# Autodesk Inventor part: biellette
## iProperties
Shininess: 20.0
Angle Display Precision: 2
Document Length Units: 11269
Document Angle Units: 11279
Document Time Units: 11290
Document Mass Units: 11283
Document Length Units Precision: 3
Document Angle Units Precision: 2
Compacted: True
Created: 2002-04
Part Number: biellette
Material: Par défaut
Document SubType Name: Modélisation
Designer: thchene
Density: 0.0
Volumn: 0.0
Area: 0.0
PropertySet Name: Model Information
Control State: 0
Master: False
Checked Out: False
Author: thchene
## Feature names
1. Extrusion1
2. Congé1 [Fillet]
3. Extrusion2
